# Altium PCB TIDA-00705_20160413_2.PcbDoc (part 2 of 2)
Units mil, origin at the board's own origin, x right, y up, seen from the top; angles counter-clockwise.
Board outline 1000 x 1000 mil, 6 copper layers (Top Layer, L2-GND-PLANE, L3-BUS, L4-BAT, L5-GND 1-PLANE, Bottom Layer), stack 0 mil thick; 66 components, 35 nets, 184 pads, 221 vias.
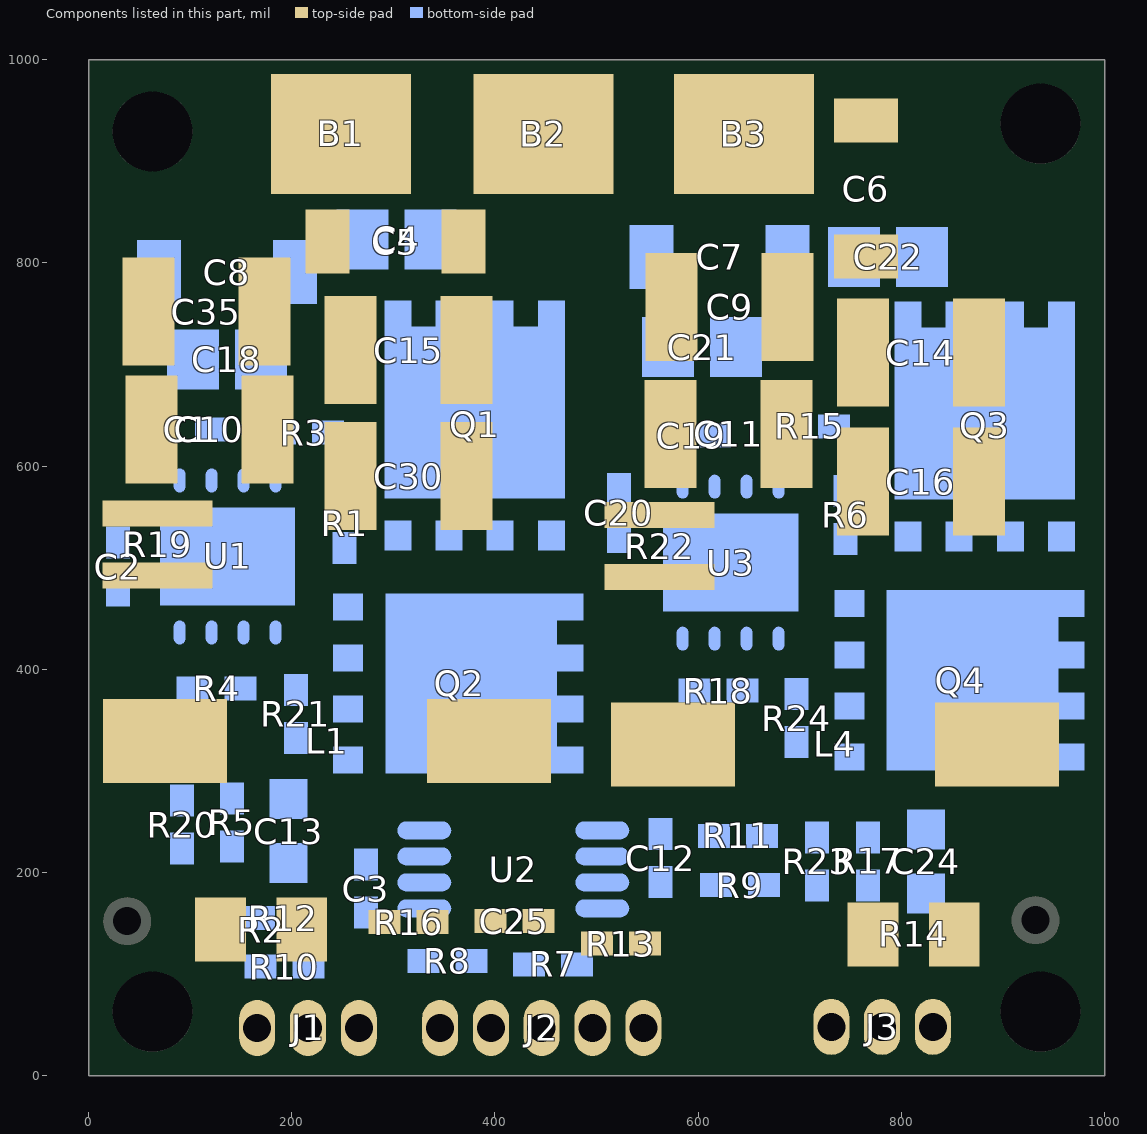
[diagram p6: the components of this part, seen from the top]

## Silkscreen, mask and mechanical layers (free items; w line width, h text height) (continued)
Drill Drawing:
  circle w1: c2013.13,1050 r25
  lines w1: 1988.13,875 2013.13,887.5 2038.13,875 2025.63,900 2038.13,925 2013.13,912.5 1988.13,925 2000.63,900 1988.13,875 ; 1988.13,1175 2038.13,1175 2038.13,1225 1988.13,1225 1988.13,1175 ; 1988.13,1337.5 2000.63,1337.5 2000.63,1325 2025.63,1325 2025.63,1337.5 2038.13,1337.5 2038.13,1362.5 2025.63,1362.5 2025.63,1375 2000.63,1375 2000.63,1362.5 1988.13,1362.5 1988.13,1337.5
  lines w15: 1920,830 5798.97,830 ; 1920,1430 5798.97,1430 ; 2470.88,680 2470.88,1580 ; 3168.69,680 3168.69,1580 ; 4514.29,680 4514.29,1580 ; 5020.17,680 5020.17,1580 ; 1920,680 5798.97,680 5798.97,1580 1920,1580 1920,680
  text "Board thickness is 1.6mm with 6 layers with 2(OZ) copper." at 6748,5313 h60
  text "As per board thickness vendor can adjust dielectric thickness." at 6738,5189 h60
  text "This is not an Impedance control board." at 6728.12,5071.45 h60
  text "Vias are filled on both sides with non conductive material." at 6749.12,4959.45 h60
  text "Symbol" at 2010,1475 h72
  text "Hit Count" at 2515.88,1475 h72
  text "Finished Hole Size" at 3213.69,1475 h72
  text "Plated" at 4559.29,1475 h72
  text "Hole Type" at 5065.17,1475 h72
  text "4" at 2515.88,1325 h60
  text "78.74mil (2.000mm)" at 3213.69,1325 h60
  text "NPTH" at 4559.29,1325 h60
  text "Round" at 5065.17,1325 h60
  text "10" at 2515.88,1175 h60
  text "7.87mil (0.200mm)" at 3213.69,1175 h60
  text "PTH" at 4559.29,1175 h60
  text "Round" at 5065.17,1175 h60
  text "13" at 2515.88,1025 h60
  text "27.56mil (0.700mm)" at 3213.69,1025 h60
  text "PTH" at 4559.29,1025 h60
  text "Round" at 5065.17,1025 h60
  text "211" at 2515.88,875 h60
  text "6.00mil (0.152mm)" at 3213.69,875 h60
  text "PTH" at 4559.29,875 h60
  text "Round" at 5065.17,875 h60
  text "238 Total" at 2515.88,725 h60
  text "Drill Table" at 1856.87,423 h60
  text "FOR 6MIL DRILL +0/-6MIL" at 1916.87,288 h60
  text "FOR 7.87MIL DRILL +0/-7.87MIL" at 1916,191 h60
  text "FOR PTH +3/-3MIL" at 1914,98 h60
  text "FOR NPTH +/- 2MIL" at 1916,-4 h60
  text ".Layer_Name" at 584.87,-858.49 h60

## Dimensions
0,1000 to 1000,1000 on M2 Board Dimensions
1000,0 to 1000,1000 on M2 Board Dimensions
